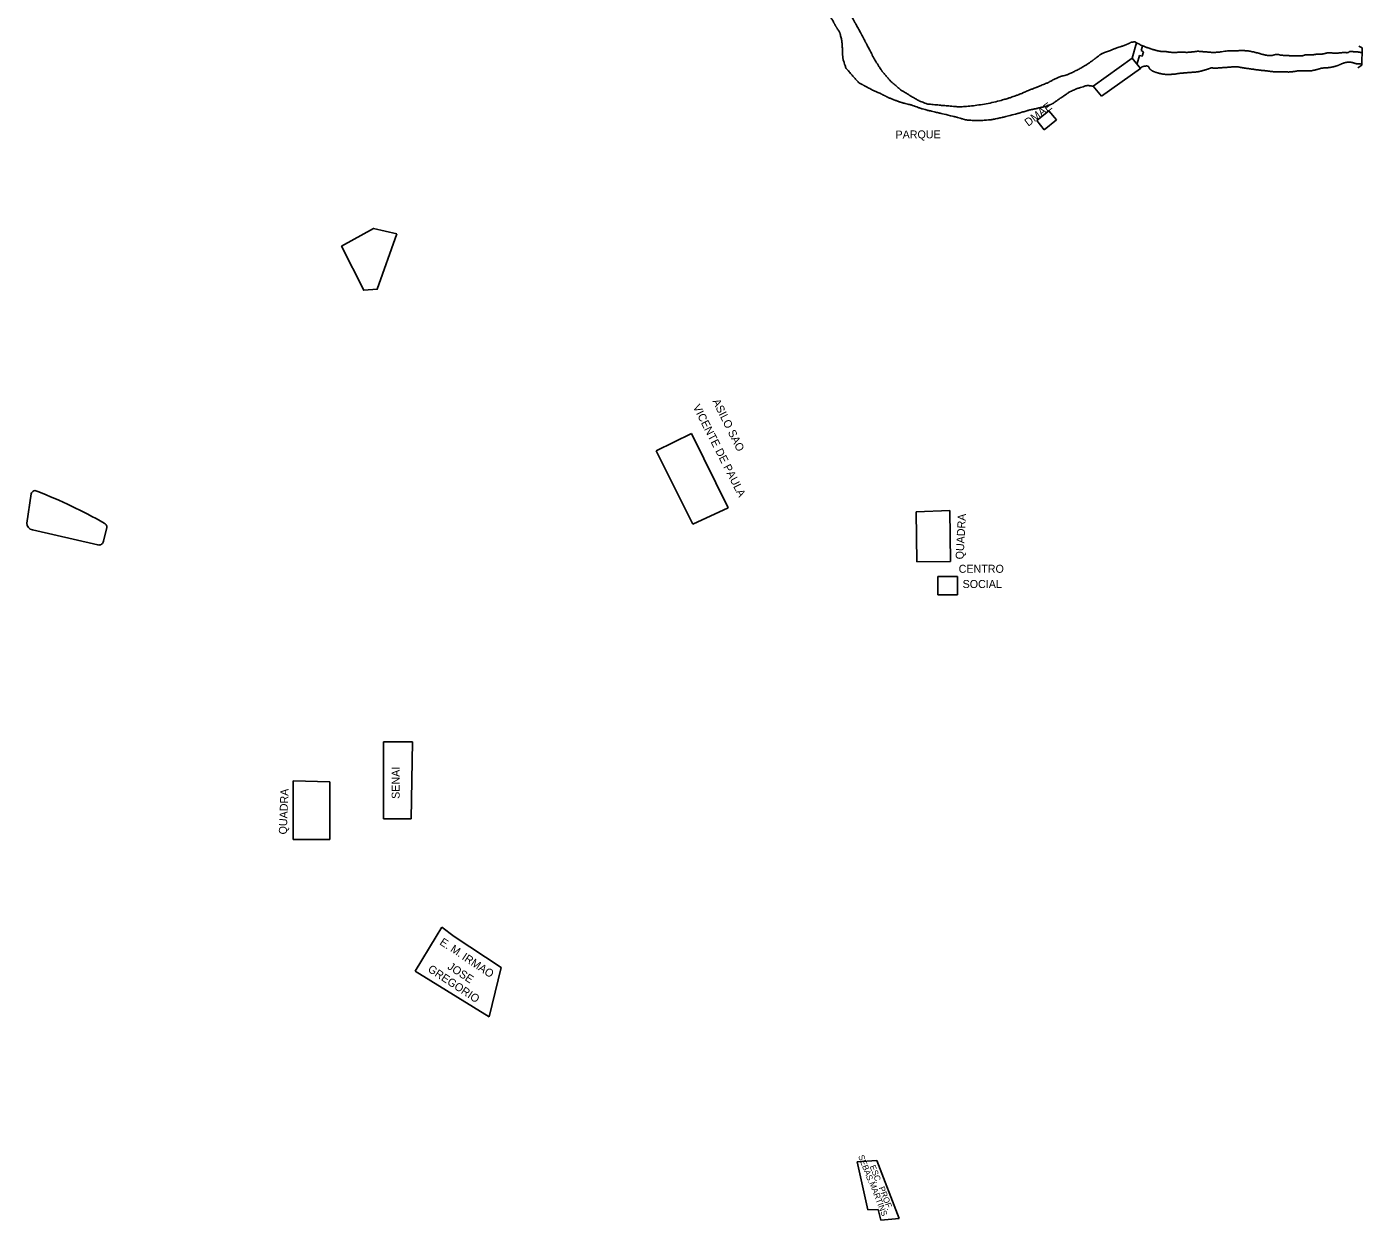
# Model space of a CAD drawing. Extents: x 325899 to 364828, y 7568995 to 7592502.
# Drawn here: x 340905 to 341572, y 7588860 to 7589457 of the extents above; entities that cross this region are included whole.
import ezdxf

# ---------------------------------------------------------------- set-up
doc = ezdxf.new("R2010")
doc.units = 0
for name, color, linetype in [('EDIFEXISTENT', 7, 'Continuous'), ('EDIFIDENTIF', 7, 'Continuous'), ('EDIFOBRAEXIS', 7, 'Continuous'), ('EDIFOBRAPROJ', 7, 'Continuous')]:
    doc.layers.add(name, color=color, linetype=linetype)

msp = doc.modelspace()

# ---------------------------------------------------------------- linework, layer by layer
at = {"layer": 'EDIFEXISTENT'}
for p, q in [((341459.12, 7589448.63), (341456.95, 7589440.9)), ((341461.98, 7589446.97), (341461.32, 7589444.71)), ((341461.32, 7589444.71), (341462.54, 7589444.13)), ((341462.54, 7589444.13), (341461.83, 7589441.82)), ((341571.87, 7589446.03), (341570.23, 7589446.81)), ((341571.58, 7589437.34), (341571.87, 7589446.03)), ((341437.48, 7589426.89), (341456.95, 7589440.9)), ((341456.95, 7589440.9), (341461.08, 7589435.79)), ((341460.49, 7589442.2), (341459.41, 7589438.18)), ((341461.83, 7589441.82), (341460.49, 7589442.2)), ((341569.68, 7589436.14), (341571.58, 7589437.34)), ((341461.08, 7589435.79), (341441.64, 7589421.88)), ((341441.64, 7589421.88), (341437.48, 7589426.89)), ((341409.18, 7589409.69), (341415.32, 7589414.6)), ((341412.99, 7589405.12), (341409.18, 7589409.69)), ((341419.03, 7589410.15), (341412.99, 7589405.12)), ((341415.32, 7589414.6), (341419.03, 7589410.15)), ((341236.68, 7589253.32), (341218.99, 7589244.68)), ((341254.97, 7589216.16), (341236.68, 7589253.32)), ((341218.99, 7589244.68), (341237.32, 7589207.91)), ((341237.32, 7589207.91), (341254.97, 7589216.16)), ((341348.91, 7589214.16), (341365.71, 7589214.72)), ((341348.91, 7589214.16), (341349.21, 7589189.21)), ((341366.11, 7589189.22), (341365.71, 7589214.72)), ((341349.21, 7589189.21), (341366.11, 7589189.22)), ((341359.75, 7589181.77), (341369.54, 7589181.77)), ((341359.79, 7589172.58), (341359.75, 7589181.77)), ((341369.54, 7589181.77), (341369.54, 7589172.58)), ((341369.54, 7589172.58), (341359.79, 7589172.58)), ((341082.71, 7589099.14), (341097.21, 7589099.19)), ((341082.71, 7589081.86), (341082.71, 7589099.14)), ((341097.21, 7589099.19), (341096.65, 7589060.63)), ((341037.67, 7589050.29), (341037.67, 7589079.63)), ((341037.67, 7589079.63), (341055.98, 7589079.15)), ((341055.98, 7589079.15), (341055.98, 7589050.29)), ((341082.71, 7589060.63), (341082.71, 7589081.86)), ((341096.65, 7589060.63), (341082.71, 7589060.63)), ((341055.98, 7589050.29), (341037.67, 7589050.29)), ((341111.96, 7589006.48), (341109.16, 7589001.91)), ((341118.09, 7589001.91), (341111.96, 7589006.48)), ((341098.59, 7588984.48), (341109.16, 7589001.91)), ((341118.09, 7589001.91), (341141.66, 7588986.37)), ((341135.6, 7588961.73), (341098.59, 7588984.48)), ((341141.66, 7588986.37), (341135.6, 7588961.73)), ((341319.49, 7588889.25), (341329.27, 7588889.83)), ((341324.81, 7588865.25), (341319.49, 7588889.25)), ((341329.27, 7588889.83), (341340.45, 7588860.91)), ((341329.92, 7588865.46), (341324.81, 7588865.25)), ((341331.25, 7588860), (341329.92, 7588865.46)), ((341340.45, 7588860.91), (341331.25, 7588860))]:
    msp.add_line(p, q, dxfattribs=at)
at = {"layer": 'EDIFOBRAEXIS'}
for points in [[(341458.18, 7589449.06), (341459.12, 7589448.63)], [(340904.5, 7589208.4), (340906.81, 7589223.07)], [(340940.12, 7589197.6), (340907.35, 7589205.09)], [(340944.6, 7589206.26), (340942.87, 7589199.49)]]:
    msp.add_lwpolyline(points, dxfattribs=at)
for centre, radius, start, end in [((340908.75, 7589222.75), 1.97, 50.13033, 170.61542), ((340827.59, 7589008.94), 230.56, 59.92271, 69.05386), ((340908.02, 7589208.54), 3.51, 182.18146, 259.0744), ((340942.11, 7589206.18), 2.49, 1.79767, 65.63222), ((340940.69, 7589199.71), 2.19, 254.82841, 354.30579)]:
    msp.add_arc(centre, radius, start, end, dxfattribs=at)
for points in [[(341259.39, 7589501.91), (341260.76, 7589500.02), (341260.76, 7589500.02), (341262.3, 7589498.38), (341262.3, 7589498.38), (341264.97, 7589496.47), (341264.97, 7589496.47), (341264.97, 7589496.47), (341268.94, 7589492.69), (341268.94, 7589492.69), (341271.12, 7589490.21), (341271.12, 7589490.21), (341273.75, 7589488.57), (341273.75, 7589488.57), (341273.75, 7589488.57), (341273.75, 7589488.57), (341275.7, 7589487.06), (341275.7, 7589487.06), (341280.23, 7589484.74), (341280.23, 7589484.74), (341284.59, 7589481.76), (341284.59, 7589481.76), (341284.59, 7589481.76), (341287.99, 7589478.4), (341287.99, 7589478.4), (341292.37, 7589474.03), (341292.37, 7589474.03), (341295.79, 7589471.1), (341295.79, 7589471.1), (341300.55, 7589468.13), (341300.55, 7589468.13), (341300.55, 7589468.13), (341300.55, 7589468.13), (341304.66, 7589464.09), (341304.66, 7589464.09), (341307.63, 7589458.93), (341307.63, 7589458.93), (341309.05, 7589456.48), (341309.05, 7589456.48), (341310.8, 7589453.62), (341310.8, 7589453.62), (341311.85, 7589449.63), (341312.03, 7589446.59), (341312.03, 7589446.59), (341312.29, 7589440.84), (341312.29, 7589440.84), (341313.79, 7589436.03), (341313.79, 7589436.03), (341313.79, 7589436.03), (341317.6, 7589431.63), (341317.6, 7589431.63), (341317.6, 7589431.63), (341320.41, 7589428.52), (341320.41, 7589428.52), (341322.94, 7589427.21), (341322.94, 7589427.21), (341327.96, 7589424.46), (341331.38, 7589423.07), (341331.38, 7589423.07), (341331.38, 7589423.07), (341332.9, 7589422.32), (341335.4, 7589421.01), (341335.4, 7589421.01), (341335.4, 7589421.01), (341335.4, 7589421.01), (341339.43, 7589419.45), (341342.09, 7589418.59), (341342.09, 7589418.59), (341346.62, 7589417.49), (341346.62, 7589417.49), (341346.62, 7589417.49), (341346.62, 7589417.49), (341351.27, 7589415.77), (341351.27, 7589415.77), (341351.27, 7589415.77), (341355.12, 7589414.72), (341355.12, 7589414.72), (341355.12, 7589414.72), (341360.49, 7589413.49), (341360.49, 7589413.49), (341360.49, 7589413.49), (341368.89, 7589411.48), (341368.89, 7589411.48), (341368.89, 7589411.48), (341373.9, 7589410), (341373.9, 7589410), (341373.9, 7589410), (341373.9, 7589410), (341379.9, 7589409.58), (341386.33, 7589410.09), (341386.33, 7589410.09), (341386.33, 7589410.09), (341386.33, 7589410.09), (341392.45, 7589411.35), (341392.45, 7589411.35), (341392.45, 7589411.35), (341392.45, 7589411.35), (341400.07, 7589413.35), (341400.07, 7589413.35), (341400.07, 7589413.35), (341400.07, 7589413.35), (341405.73, 7589415.04), (341405.73, 7589415.04), (341409.03, 7589415.68), (341409.03, 7589415.68), (341414.04, 7589416.9), (341416.85, 7589417.99), (341416.85, 7589417.99), (341422.47, 7589421.86), (341422.47, 7589421.86), (341422.47, 7589421.86), (341425.62, 7589424.06), (341425.62, 7589424.06), (341425.62, 7589424.06), (341429.76, 7589425.83), (341429.76, 7589425.83), (341429.76, 7589425.83), (341434.44, 7589427.26), (341434.44, 7589427.26), (341434.44, 7589427.26), (341437.48, 7589426.89)], [(341274.39, 7589501.91), (341276.14, 7589500.21), (341276.14, 7589500.21), (341276.14, 7589500.21), (341280.29, 7589497.87), (341280.29, 7589497.87), (341280.29, 7589497.87), (341283.31, 7589496.55), (341285.96, 7589494.83), (341285.96, 7589494.83), (341285.96, 7589494.83), (341285.96, 7589494.83), (341289.4, 7589492), (341289.4, 7589492), (341289.4, 7589492), (341292.42, 7589488.51), (341292.42, 7589488.51), (341292.42, 7589488.51), (341294.73, 7589485.06), (341296.27, 7589483.7), (341299.01, 7589480.76), (341301.58, 7589477.34), (341301.58, 7589477.34), (341301.58, 7589477.34), (341305.33, 7589473.55), (341305.33, 7589473.55), (341309.07, 7589469.96), (341309.07, 7589469.96), (341309.07, 7589469.96), (341309.07, 7589469.96), (341313.75, 7589466.06), (341313.75, 7589466.06), (341313.75, 7589466.06), (341316.04, 7589462.87), (341316.04, 7589462.87), (341318.56, 7589458.42), (341318.56, 7589458.42), (341318.56, 7589458.42), (341321.65, 7589452.72), (341321.65, 7589452.72), (341323.53, 7589449.12), (341323.53, 7589449.12), (341326.73, 7589443.07), (341326.73, 7589443.07), (341327.67, 7589441.04), (341327.67, 7589441.04), (341331.96, 7589434.28), (341331.96, 7589434.28), (341331.96, 7589434.28), (341336.17, 7589429.42), (341336.17, 7589429.42), (341341.07, 7589425.15), (341341.07, 7589425.15), (341345.53, 7589422.42), (341345.53, 7589422.42), (341350.45, 7589419.53), (341350.45, 7589419.53), (341354.46, 7589417.99), (341354.46, 7589417.99), (341354.46, 7589417.99), (341354.46, 7589417.99), (341362.85, 7589417.19), (341362.85, 7589417.19), (341362.85, 7589417.19), (341370.65, 7589416.53), (341370.65, 7589416.53), (341378.12, 7589417.14), (341386.43, 7589418.47), (341394.49, 7589420.66), (341394.49, 7589420.66), (341399.93, 7589422.56), (341399.93, 7589422.56), (341399.93, 7589422.56), (341405.63, 7589424.98), (341409.51, 7589426.48), (341409.51, 7589426.48), (341415.05, 7589428.74), (341415.05, 7589428.74), (341415.05, 7589428.74), (341419.84, 7589431.41), (341424.24, 7589432.52), (341424.24, 7589432.52), (341424.24, 7589432.52), (341424.24, 7589432.52), (341424.24, 7589432.52), (341429.94, 7589435.12), (341435.08, 7589438.27), (341435.08, 7589438.27), (341437.34, 7589439.9), (341437.34, 7589439.9), (341437.34, 7589439.9), (341441.54, 7589443.06), (341441.54, 7589443.06), (341441.54, 7589443.06), (341447.74, 7589445.48), (341447.74, 7589445.48), (341453.92, 7589447.59), (341453.92, 7589447.59), (341453.92, 7589447.59), (341456.37, 7589448.83), (341456.37, 7589448.83), (341458.18, 7589449.06)], [(341459.12, 7589448.63), (341461.98, 7589446.97), (341465.4, 7589445.86), (341466.59, 7589445.4), (341468.75, 7589444.8), (341469.86, 7589444.54), (341470.75, 7589444.29), (341473.03, 7589444.24), (341474.22, 7589444.14), (341476.1, 7589443.79), (341478.96, 7589443.74), (341480.18, 7589443.9), (341482.58, 7589443.88), (341484.46, 7589443.75), (341487.63, 7589444.08), (341488.92, 7589444.26), (341489.75, 7589444.37), (341492.85, 7589444.09), (341495.56, 7589443.89), (341497.41, 7589443.67), (341499.13, 7589443.85), (341499.81, 7589443.82), (341504.83, 7589444.61), (341508.76, 7589444.59), (341511.47, 7589444.7), (341514.91, 7589444.58), (341519.53, 7589443.54), (341522.34, 7589442.66), (341524.42, 7589442.26), (341526.4, 7589442.11), (341526.85, 7589442.23), (341528.27, 7589442.69), (341529.76, 7589442.8), (341531.03, 7589442.37), (341533.77, 7589442.22), (341535.69, 7589442.12), (341537.04, 7589442.09), (341539.27, 7589442), (341542.13, 7589442.08), (341542.92, 7589442.36), (341543.52, 7589442.64), (341546.31, 7589442.59), (341547.58, 7589442.59), (341548.72, 7589442.87), (341550.87, 7589442.82), (341551.63, 7589442.9), (341552.87, 7589443.13), (341554.52, 7589443.59), (341556.24, 7589443.59), (341557.69, 7589443.34), (341559.61, 7589443.39), (341561.28, 7589443.65), (341563.41, 7589443.67), (341564.78, 7589443.6), (341565.72, 7589444.34), (341566.71, 7589444.21), (341568.1, 7589444.03), (341569.14, 7589444.09), (341571.82, 7589443.68)], [(341461.08, 7589435.79), (341461.36, 7589436.37), (341462.96, 7589436.96), (341465.01, 7589437.01), (341465.52, 7589435.64), (341466.1, 7589435.11), (341467.09, 7589434.43), (341468.05, 7589434.05), (341469.35, 7589433.57), (341472.18, 7589432.92), (341474.62, 7589432.67), (341478.34, 7589432.92), (341480.55, 7589433.33), (341483.86, 7589433.59), (341486.57, 7589433.82), (341489.89, 7589434.05), (341492.45, 7589434.74), (341495.82, 7589435.78), (341496.53, 7589436.14), (341497.85, 7589435.79), (341501.8, 7589436.15), (341504.16, 7589436.28), (341506.92, 7589436.53), (341509.27, 7589436.64), (341511.96, 7589436.11), (341515.13, 7589435.66), (341517.59, 7589435.3), (341521.95, 7589434.73), (341523.97, 7589434.58), (341527.34, 7589434.08), (341530.31, 7589434.08), (341533.1, 7589434.01), (341535.43, 7589433.96), (341536.54, 7589434.06), (341538.87, 7589434.37), (341539.94, 7589434.65), (341543.71, 7589434.58), (341546.24, 7589434.48), (341549.59, 7589435.32), (341551.82, 7589436.01), (341555.11, 7589436.11), (341558.4, 7589436.78), (341559.92, 7589437.31), (341561.57, 7589438.12), (341563.24, 7589438.68), (341565.19, 7589438.99), (341566.08, 7589438.86), (341567.12, 7589438.69), (341568.23, 7589438.26), (341569.65, 7589438.01), (341571.6, 7589437.96)]]:
    msp.add_open_spline(points, degree=2, dxfattribs=at)
at = {"layer": 'EDIFOBRAPROJ'}
msp.add_lwpolyline([(341089.43, 7589353.07), (341079.63, 7589325.36), (341072.92, 7589324.87), (341061.82, 7589346.9), (341077.82, 7589355.82), (341089.43, 7589353.07)], dxfattribs=at)

# ---------------------------------------------------------------- texts
at = {"layer": 'EDIFIDENTIF'}
for s, height, rotation, p in [('DMAE', 4, 37.32288, (341404.98, 7589406.58)), ('PARQUE', 4, 0.37553, (341338.63, 7589400.7)), ('ASILO SAO', 4, 296.46344, (341247.03, 7589269.41)), ('VICENTE DE PAULA', 4, 296.95882, (341237.25, 7589266.6)), ('QUADRA', 4, 86.99388, (341372.62, 7589190.27)), ('SENAI', 4, 90, (341090.86, 7589070.66)), ('QUADRA', 4, 87.79363, (341034.45, 7589052.81)), ('E.', 4, 326.58931, (341110.5, 7588998.1)), ('M.', 4, 326.58931, (341115.88, 7588994.67)), ('IRMAO', 4, 326.58931, (341121.62, 7588990.64)), ('GREGORIO', 4, 326.58931, (341104.56, 7588984.65)), ('JOSE', 4, 326.58931, (341114.44, 7588985.93)), ('SEBAS.', 3, 291.13531, (341319.92, 7588892.02)), ('ESC.', 3, 291.13531, (341325.66, 7588886.94)), ('MARTINS', 3, 291.13531, (341325.42, 7588878.62)), ('PROF.', 3, 291.13531, (341330.17, 7588876.24))]:
    msp.add_text(s, height=height, rotation=rotation, dxfattribs=at).set_placement(p)
for s, p in [('CENTRO ', (341370.19, 7589183.66)), ('SOCIAL', (341372.16, 7589176.05))]:
    msp.add_text(s, height=4, dxfattribs=at).set_placement(p)

doc.saveas('drawing.dxf')
